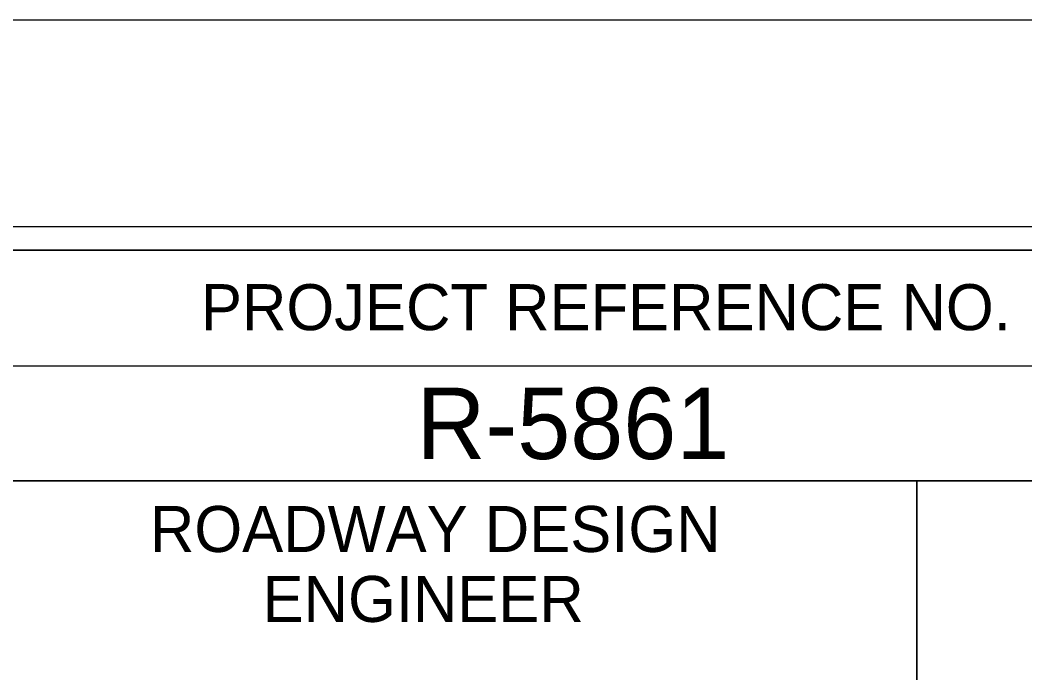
# Model space of a CAD drawing. Extents: x 505237 to 506921, y 424821 to 425921.
# Drawn here: x 506706.2 to 506815.5, y 425849.7 to 425920.7 of the extents above; entities that cross this region are included whole.
import ezdxf

# ---------------------------------------------------------------- set-up
doc = ezdxf.new("R2010")
doc.units = 0
for name, color, linetype in [('Prop Horizontal Alignment Station Label', 7, 'Continuous'), ('Sheet Cutting Line CELL', 7, 'Continuous'), ('Sheet Data Field CELL', 7, 'Continuous'), ('Sheet Plot Border Inside CELL', 7, 'Continuous'), ('Sheet Plot Border Outside CELL', 7, 'Continuous'), ('Sheet Sticker Incomplete CELL', 7, 'Continuous')]:
    doc.layers.add(name, color=color, linetype=linetype)

msp = doc.modelspace()

# ---------------------------------------------------------------- linework, layer by layer
at = {"layer": 'Prop Horizontal Alignment Station Label'}
for p, q in [((506703.66, 425883.12), (506903.71, 425883.12)), ((506803.71, 425870.62), (506803.71, 425758.17))]:
    msp.add_line(p, q, dxfattribs=at)
for points in [[(506903.71, 425895.67), (505403.71, 425895.67), (505403.71, 424845.67), (506903.71, 424845.67)], [(506703.66, 425895.67), (506903.71, 425895.67), (506903.71, 425870.62), (506703.66, 425870.62)], [(506703.66, 425870.62), (506803.71, 425870.62), (506803.71, 425758.12), (506703.66, 425758.12)], [(506803.71, 425870.62), (506903.71, 425870.62), (506903.71, 425758.12), (506803.71, 425758.12)]]:
    msp.add_lwpolyline(points, close=True, dxfattribs=at)
at = {"layer": 'Sheet Cutting Line CELL'}
msp.add_line((506920.71, 425920.67), (505236.71, 425920.67), dxfattribs=at)
msp.add_lwpolyline([(506353.71, 425395.67), (506403.71, 425395.67), (506403.71, 425895.67), (506453.71, 425895.67), (506453.71, 425395.67), (506503.71, 425395.67), (506503.71, 425895.67), (506553.71, 425895.67), (506553.71, 425395.67), (506603.71, 425395.67), (506603.71, 425895.67), (506653.71, 425895.67), (506653.71, 425395.67), (506703.71, 425395.67), (506703.71, 425895.67), (506730.01, 425895.67)], dxfattribs=at)
at = {"layer": 'Sheet Plot Border Inside CELL'}
msp.add_lwpolyline([(505249.71, 424843.12), (506916.21, 424843.12), (506916.21, 425898.22), (505249.71, 425898.22)], close=True, dxfattribs=at)
at = {"layer": 'Sheet Plot Border Outside CELL'}
msp.add_lwpolyline([(505236.71, 424820.67), (506920.71, 424820.67), (506920.71, 425920.67), (505236.71, 425920.67)], close=True, dxfattribs=at)
at = {"layer": 'Sheet Sticker Incomplete CELL'}
msp.add_lwpolyline([(506698.71, 425395.67), (506698.71, 425895.67), (506708.71, 425895.67)], dxfattribs=at)

# ---------------------------------------------------------------- texts
at = {"layer": 'Prop Horizontal Alignment Station Label'}
for s, height, p in [('PROJECT REFERENCE NO.', 5.0001, (506725.88, 425886.98)), ('ROADWAY DESIGN', 5.0001, (506720.33, 425862.88)), ('ENGINEER', 5, (506732.58, 425855.28))]:
    msp.add_text(s, height=height, dxfattribs=at).set_placement(p)
at = {"layer": 'Sheet Data Field CELL'}
msp.add_text('R-5861', height=7.75, dxfattribs=at).set_placement((506749.33, 425872.98))

doc.saveas('drawing.dxf')
